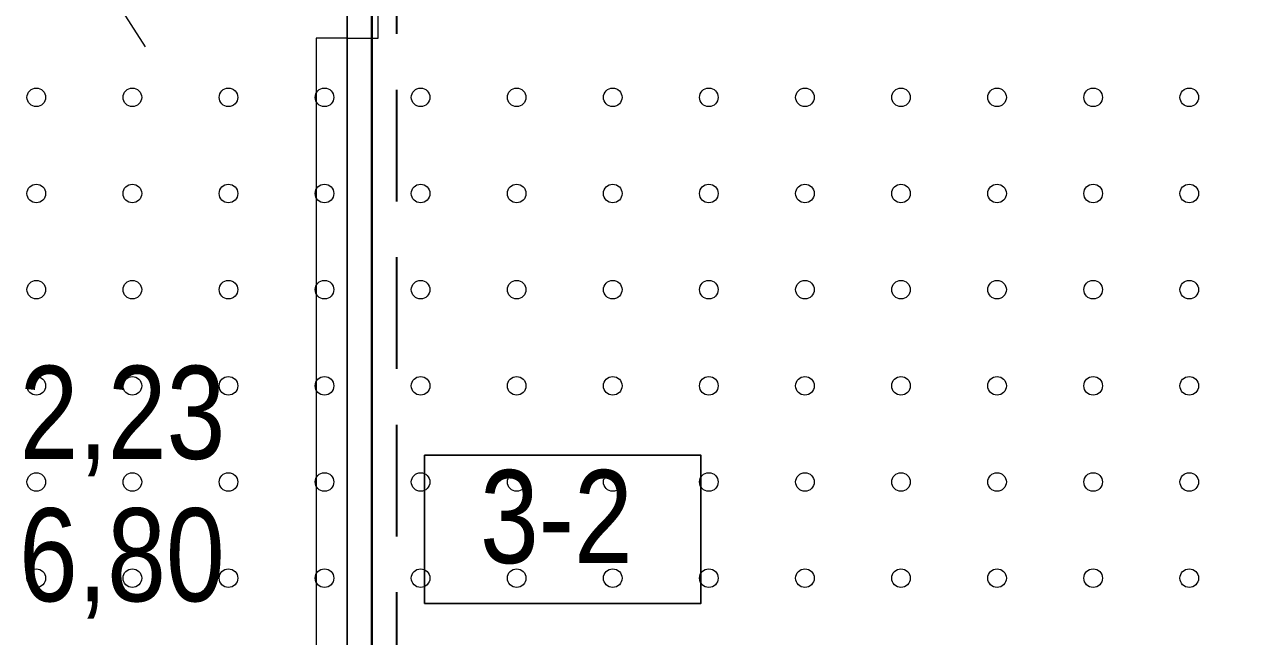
# Model space of a CAD drawing. Extents: x 640121 to 640955, y 6441885 to 6442246.
# Drawn here: x 640163.96 to 640203.3, y 6442150.71 to 6442170.45 of the extents above; entities that cross this region are included whole.
import ezdxf
from ezdxf.enums import TextEntityAlignment as Align

# ---------------------------------------------------------------- set-up
doc = ezdxf.new("R2010")
doc.units = 0
doc.header["$LTSCALE"] = 1.2
doc.linetypes.add('MEDIUM_DASHED', pattern=[4.5, 3, -1.5])
for name, color, linetype, lineweight in [('31', 7, 'Continuous', 13), ('32', 7, 'Continuous', 13), ('33', 7, 'Continuous', 13), ('35', 7, 'Continuous', 35), ('43', 7, 'Continuous', 13)]:
    doc.layers.add(name, color=color, linetype=linetype, lineweight=lineweight)

msp = doc.modelspace()

# ---------------------------------------------------------------- linework, layer by layer
at = {"layer": '31'}
msp.add_line((640166.93, 6442171.16), (640167.86, 6442169.72), dxfattribs=at)
at = {"layer": '32', "lineweight": 25}
msp.add_line((640174.37, 6442195.09), (640174.37, 6442080), dxfattribs=at)
at = {"layer": '33'}
for points in [[(640175.37, 6442170), (640175.37, 6442196), (640174.37, 6442196), (640174.37, 6442170)], [(640173.37, 6442170), (640173.37, 6442140), (640174.37, 6442140), (640174.37, 6442170)]]:
    msp.add_lwpolyline(points, close=True, dxfattribs=at)
at = {"layer": '33', "lineweight": 25}
msp.add_lwpolyline([(640176.87, 6442156.56), (640185.79, 6442156.56), (640185.79, 6442151.78), (640176.87, 6442151.78)], close=True, dxfattribs=at)
at = {"layer": '35', "linetype": 'MEDIUM_DASHED'}
msp.add_line((640175.97, 6442195.34), (640175.97, 6442105.93), dxfattribs=at)
at = {"layer": '35', "lineweight": 40}
msp.add_lwpolyline([(640175.17, 6442195.66), (640175.17, 6442085.83), (640261.07, 6442089.76)], dxfattribs=at)
at = {"layer": '43'}
for centre in [(640164.344, 6442168.096), (640167.444, 6442168.096), (640170.544, 6442168.096), (640173.644, 6442168.096), (640176.744, 6442168.096), (640179.844, 6442168.096), (640182.944, 6442168.096), (640186.044, 6442168.096), (640189.144, 6442168.096), (640192.244, 6442168.096), (640195.344, 6442168.096), (640198.444, 6442168.096), (640201.544, 6442168.096), (640164.344, 6442164.996), (640167.444, 6442164.996), (640170.544, 6442164.996), (640173.644, 6442164.996), (640176.744, 6442164.996), (640179.844, 6442164.996), (640182.944, 6442164.996), (640186.044, 6442164.996), (640189.144, 6442164.996), (640192.244, 6442164.996), (640195.344, 6442164.996), (640198.444, 6442164.996), (640201.544, 6442164.996), (640164.344, 6442161.896), (640167.444, 6442161.896), (640170.544, 6442161.896), (640173.644, 6442161.896), (640176.744, 6442161.896), (640179.844, 6442161.896), (640182.944, 6442161.896), (640186.044, 6442161.896), (640189.144, 6442161.896), (640192.244, 6442161.896), (640195.344, 6442161.896), (640198.444, 6442161.896), (640201.544, 6442161.896), (640164.344, 6442158.796), (640167.444, 6442158.796), (640170.544, 6442158.796), (640173.644, 6442158.796), (640176.744, 6442158.796), (640179.844, 6442158.796), (640182.944, 6442158.796), (640186.044, 6442158.796), (640189.144, 6442158.796), (640192.244, 6442158.796), (640195.344, 6442158.796), (640198.444, 6442158.796), (640201.544, 6442158.796), (640164.344, 6442155.696), (640167.444, 6442155.696), (640170.544, 6442155.696), (640173.644, 6442155.696), (640176.744, 6442155.696), (640179.844, 6442155.696), (640182.944, 6442155.696), (640186.044, 6442155.696), (640189.144, 6442155.696), (640192.244, 6442155.696), (640195.344, 6442155.696), (640198.444, 6442155.696), (640201.544, 6442155.696), (640164.344, 6442152.596), (640167.444, 6442152.596), (640170.544, 6442152.596), (640173.644, 6442152.596), (640176.744, 6442152.596), (640179.844, 6442152.596), (640182.944, 6442152.596), (640186.044, 6442152.596), (640189.144, 6442152.596), (640192.244, 6442152.596), (640195.344, 6442152.596), (640198.444, 6442152.596), (640201.544, 6442152.596)]:
    msp.add_circle(centre, 0.3, dxfattribs=at)

# ---------------------------------------------------------------- texts
at = {"layer": '32', "width": 0.85}
msp.add_text('2,23', height=3, dxfattribs=at).set_placement((640167.125, 6442156.44), align=Align.CENTER)
at = {"layer": '33', "width": 0.85}
for s, p in [('3-2', (640181.125, 6442153.08)), ('6,80', (640167.105, 6442151.85))]:
    msp.add_text(s, height=3, dxfattribs=at).set_placement(p, align=Align.CENTER)

doc.saveas('drawing.dxf')
